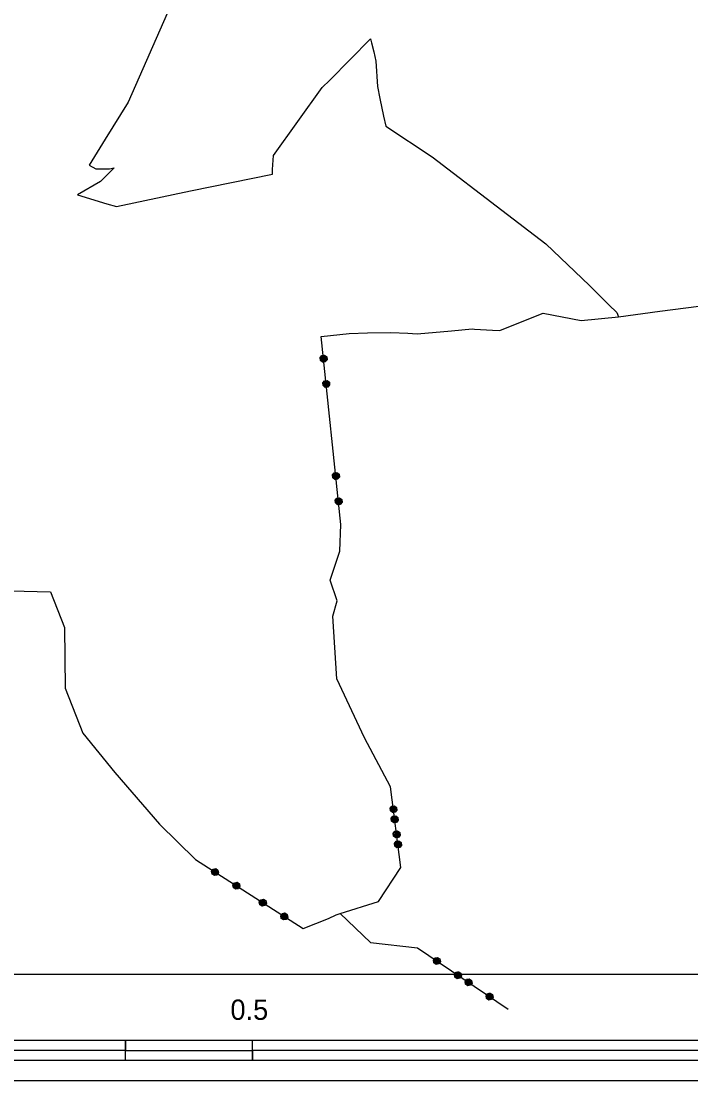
# Model space of a CAD drawing. Extents: x -783999 to -781353, y -1138035 to -1135203.
# Drawn here: x -783274 to -782747, y -1138035 to -1137201 of the extents above; entities that cross this region are included whole.
import ezdxf

# ---------------------------------------------------------------- set-up
doc = ezdxf.new("R2010")
doc.units = 0
for name, color, linetype in [('GR_MER', 7, 'Continuous'), ('HRA_KU', 7, 'Continuous'), ('OVNE_PRE', 7, 'Continuous'), ('OVNE_SET', 7, 'Continuous')]:
    doc.layers.add(name, color=color, linetype=linetype)

msp = doc.modelspace()

# ---------------------------------------------------------------- linework, layer by layer
at = {"layer": 'GR_MER'}
for points in [[(-781937.12, -1137951.24), (-781937.12, -1138035.25), (-783615.31, -1138035.25), (-783615.31, -1137951.24), (-781937.12, -1137951.24)], [(-783192.03, -1138011.25), (-783192.03, -1138003.25), (-783092.03, -1138003.25)], [(-783192.03, -1138019.25), (-783292.03, -1138019.25), (-783292.03, -1138011.25)], [(-782592.03, -1138019.25), (-783092.03, -1138019.25), (-783092.03, -1138011.25)]]:
    msp.add_lwpolyline(points, dxfattribs=at)
for points in [[(-783192.03, -1138011.25), (-783292.03, -1138011.25), (-783292.03, -1138003.25), (-783192.03, -1138003.25)], [(-782592.03, -1138011.25), (-783092.03, -1138011.25), (-783092.03, -1138003.25), (-782592.03, -1138003.25)], [(-783092.03, -1138019.25), (-783192.03, -1138019.25), (-783192.03, -1138011.25), (-783092.03, -1138011.25)]]:
    msp.add_lwpolyline(points, close=True, dxfattribs=at)
at = {"layer": 'HRA_KU'}
for points in [[(-783022.89, -1137903.48), (-782992.86, -1137893.9), (-782975.31, -1137867.31), (-782983.29, -1137803.78), (-783003.83, -1137765.01), (-783025.51, -1137718.72), (-783028.67, -1137669.18), (-783025.47, -1137657.3), (-783030.85, -1137641.03), (-783023.21, -1137618.17), (-783022.37, -1137597.08), (-783037.93, -1137448.95), (-783015.95, -1137446.62), (-783001.44, -1137446.28), (-782983.19, -1137445.77), (-782969.65, -1137446.47), (-782962.27, -1137446.92), (-782935.25, -1137444.56), (-782919.09, -1137443.08), (-782917.36, -1137443.17), (-782902.99, -1137444.14), (-782897.35, -1137444.43), (-782865.42, -1137431.53), (-782863.19, -1137430.59), (-782833.35, -1137436.41), (-782803.82, -1137433.57)], [(-783038.74, -1137465.69), (-783037.39, -1137464.02), (-783035.24, -1137463.79), (-783033.57, -1137465.14), (-783033.34, -1137467.29), (-783034.7, -1137468.96), (-783036.85, -1137469.19), (-783038.52, -1137467.83), (-783038.74, -1137465.69), (-783038.4, -1137465.89), (-783038.2, -1137467.8), (-783037.49, -1137468.37), (-783037.83, -1137465.19), (-783037.26, -1137464.48), (-783036.79, -1137468.94), (-783036.16, -1137468.87), (-783036.62, -1137464.42), (-783035.98, -1137464.35), (-783035.52, -1137468.81), (-783034.88, -1137468.74), (-783035.35, -1137464.28), (-783034.65, -1137464.85), (-783034.31, -1137468.04), (-783033.74, -1137467.33), (-783033.94, -1137465.42)], [(-783036.66, -1137485.58), (-783035.31, -1137483.91), (-783033.16, -1137483.68), (-783031.49, -1137485.04), (-783031.26, -1137487.18), (-783032.62, -1137488.85), (-783034.77, -1137489.08), (-783036.44, -1137487.72), (-783036.66, -1137485.58), (-783036.33, -1137485.62), (-783036.13, -1137487.53), (-783035.43, -1137488.1), (-783035.76, -1137484.92), (-783035.19, -1137484.22), (-783034.73, -1137488.67), (-783034.09, -1137488.61), (-783034.56, -1137484.15), (-783033.92, -1137484.08), (-783033.46, -1137488.54), (-783032.82, -1137488.47), (-783033.28, -1137484.02), (-783032.58, -1137484.59), (-783032.25, -1137487.77), (-783031.68, -1137487.07), (-783031.88, -1137485.16)], [(-783029.03, -1137558.12), (-783027.68, -1137556.45), (-783025.53, -1137556.23), (-783023.86, -1137557.58), (-783023.63, -1137559.73), (-783024.99, -1137561.4), (-783027.14, -1137561.62), (-783028.81, -1137560.27), (-783029.03, -1137558.12), (-783028.69, -1137558.33), (-783028.49, -1137560.24), (-783027.79, -1137560.81), (-783028.12, -1137557.62), (-783027.55, -1137556.92), (-783027.08, -1137561.38), (-783026.45, -1137561.31), (-783026.91, -1137556.85), (-783026.27, -1137556.79), (-783025.81, -1137561.24), (-783025.17, -1137561.18), (-783025.64, -1137556.72), (-783024.94, -1137557.29), (-783024.6, -1137560.47), (-783024.03, -1137559.77), (-783024.23, -1137557.86)], [(-783026.95, -1137578.01), (-783025.6, -1137576.34), (-783023.45, -1137576.12), (-783021.78, -1137577.47), (-783021.55, -1137579.62), (-783022.91, -1137581.29), (-783025.06, -1137581.51), (-783026.73, -1137580.16), (-783026.95, -1137578.01), (-783026.62, -1137578.06), (-783026.42, -1137579.97), (-783025.72, -1137580.54), (-783026.05, -1137577.36), (-783025.48, -1137576.65), (-783025.02, -1137581.11), (-783024.38, -1137581.04), (-783024.85, -1137576.59), (-783024.21, -1137576.52), (-783023.75, -1137580.98), (-783023.11, -1137580.91), (-783023.57, -1137576.45), (-783022.87, -1137577.02), (-783022.54, -1137580.21), (-783021.97, -1137579.5), (-783022.17, -1137577.59)], [(-783303.13, -1137648.78), (-783250.99, -1137650.16), (-783239.9, -1137678.31), (-783239.48, -1137726.05), (-783225.61, -1137761.46), (-783200.39, -1137792.47), (-783165.09, -1137833.16), (-783136.89, -1137860.91), (-783052.16, -1137915.26), (-783032.08, -1137907.33), (-783026.02, -1137904.41), (-783022.89, -1137903.48)], [(-782983.77, -1137820.53), (-782982.45, -1137818.83), (-782980.31, -1137818.56), (-782978.61, -1137819.88), (-782978.34, -1137822.02), (-782979.66, -1137823.72), (-782981.8, -1137823.99), (-782983.5, -1137822.67), (-782983.77, -1137820.53), (-782983.42, -1137820.73), (-782983.18, -1137822.63), (-782982.47, -1137823.19), (-782982.87, -1137820.01), (-782982.31, -1137819.3), (-782981.75, -1137823.74), (-782981.12, -1137823.66), (-782981.68, -1137819.22), (-782981.04, -1137819.14), (-782980.48, -1137823.58), (-782979.85, -1137823.5), (-782980.41, -1137819.06), (-782979.69, -1137819.61), (-782979.29, -1137822.79), (-782978.74, -1137822.07), (-782978.98, -1137820.17)], [(-782982.77, -1137828.5), (-782981.45, -1137826.8), (-782979.31, -1137826.53), (-782977.61, -1137827.85), (-782977.34, -1137829.99), (-782978.66, -1137831.69), (-782980.8, -1137831.96), (-782982.5, -1137830.64), (-782982.77, -1137828.5), (-782982.42, -1137828.7), (-782982.18, -1137830.6), (-782981.47, -1137831.16), (-782981.87, -1137827.98), (-782981.31, -1137827.27), (-782980.75, -1137831.71), (-782980.12, -1137831.63), (-782980.68, -1137827.19), (-782980.04, -1137827.11), (-782979.48, -1137831.55), (-782978.85, -1137831.47), (-782979.41, -1137827.03), (-782978.69, -1137827.58), (-782978.29, -1137830.76), (-782977.74, -1137830.04), (-782977.98, -1137828.14)], [(-782981.27, -1137840.37), (-782979.95, -1137838.68), (-782977.81, -1137838.41), (-782976.11, -1137839.73), (-782975.84, -1137841.87), (-782977.16, -1137843.57), (-782979.3, -1137843.84), (-782981, -1137842.52), (-782981.27, -1137840.37), (-782980.94, -1137840.41), (-782980.7, -1137842.32), (-782979.99, -1137842.87), (-782980.39, -1137839.7), (-782979.83, -1137838.98), (-782979.27, -1137843.43), (-782978.64, -1137843.35), (-782979.2, -1137838.9), (-782978.56, -1137838.82), (-782978, -1137843.27), (-782977.37, -1137843.19), (-782977.93, -1137838.74), (-782977.21, -1137839.3), (-782976.81, -1137842.47), (-782976.26, -1137841.76), (-782976.5, -1137839.85)], [(-782980.27, -1137848.34), (-782978.95, -1137846.64), (-782976.81, -1137846.37), (-782975.11, -1137847.69), (-782974.84, -1137849.83), (-782976.16, -1137851.53), (-782978.3, -1137851.8), (-782980, -1137850.48), (-782980.27, -1137848.34), (-782979.94, -1137848.38), (-782979.7, -1137850.29), (-782978.99, -1137850.84), (-782979.39, -1137847.67), (-782978.83, -1137846.95), (-782978.27, -1137851.4), (-782977.64, -1137851.32), (-782978.2, -1137846.87), (-782977.56, -1137846.79), (-782977, -1137851.24), (-782976.37, -1137851.16), (-782976.93, -1137846.71), (-782976.21, -1137847.27), (-782975.81, -1137850.44), (-782975.26, -1137849.73), (-782975.5, -1137847.82)], [(-783119.15, -1137869.25), (-783118.69, -1137871.35), (-783119.85, -1137873.17), (-783121.95, -1137873.63), (-783123.77, -1137872.46), (-783124.23, -1137870.36), (-783123.06, -1137868.55), (-783120.96, -1137868.09), (-783119.15, -1137869.25), (-783119.39, -1137869.48), (-783121, -1137868.44), (-783121.89, -1137868.64), (-783119.19, -1137870.36), (-783119, -1137871.25), (-783122.77, -1137868.83), (-783123.12, -1137869.37), (-783119.34, -1137871.79), (-783119.69, -1137872.32), (-783123.46, -1137869.91), (-783123.81, -1137870.44), (-783120.04, -1137872.86), (-783120.92, -1137873.06), (-783123.61, -1137871.33), (-783123.42, -1137872.21), (-783121.8, -1137873.25)], [(-783102.31, -1137880.05), (-783101.85, -1137882.15), (-783103.02, -1137883.97), (-783105.12, -1137884.43), (-783106.94, -1137883.26), (-783107.39, -1137881.16), (-783106.23, -1137879.34), (-783104.13, -1137878.88), (-783102.31, -1137880.05), (-783102.68, -1137880.19), (-783104.3, -1137879.15), (-783105.19, -1137879.34), (-783102.49, -1137881.07), (-783102.3, -1137881.96), (-783106.07, -1137879.54), (-783106.41, -1137880.08), (-783102.64, -1137882.49), (-783102.99, -1137883.03), (-783106.76, -1137880.62), (-783107.11, -1137881.15), (-783103.33, -1137883.57), (-783104.22, -1137883.77), (-783106.91, -1137882.04), (-783106.72, -1137882.92), (-783105.1, -1137883.96)], [(-783081.55, -1137893.37), (-783081.09, -1137895.47), (-783082.26, -1137897.28), (-783084.36, -1137897.74), (-783086.18, -1137896.58), (-783086.64, -1137894.48), (-783085.47, -1137892.66), (-783083.37, -1137892.2), (-783081.55, -1137893.37), (-783081.79, -1137893.59), (-783083.41, -1137892.56), (-783084.29, -1137892.75), (-783081.6, -1137894.48), (-783081.41, -1137895.36), (-783085.18, -1137892.94), (-783085.52, -1137893.48), (-783081.75, -1137895.9), (-783082.1, -1137896.44), (-783085.87, -1137894.02), (-783086.21, -1137894.56), (-783082.44, -1137896.98), (-783083.33, -1137897.17), (-783086.02, -1137895.44), (-783085.83, -1137896.33), (-783084.21, -1137897.36)], [(-783064.72, -1137904.16), (-783064.26, -1137906.26), (-783065.42, -1137908.08), (-783067.52, -1137908.54), (-783069.34, -1137907.37), (-783069.8, -1137905.27), (-783068.63, -1137903.46), (-783066.53, -1137903), (-783064.72, -1137904.16), (-783065.09, -1137904.3), (-783066.71, -1137903.27), (-783067.59, -1137903.46), (-783064.9, -1137905.19), (-783064.7, -1137906.07), (-783068.48, -1137903.65), (-783068.82, -1137904.19), (-783065.05, -1137906.61), (-783065.4, -1137907.15), (-783069.17, -1137904.73), (-783069.51, -1137905.27), (-783065.74, -1137907.69), (-783066.62, -1137907.88), (-783069.32, -1137906.15), (-783069.13, -1137907.04), (-783067.51, -1137908.07)], [(-783022.89, -1137903.48), (-782999.02, -1137926.43), (-782962.01, -1137930.52), (-782890.78, -1137978.73)], [(-782944.47, -1137939.3), (-782944.07, -1137941.41), (-782945.28, -1137943.19), (-782947.39, -1137943.6), (-782949.18, -1137942.39), (-782949.59, -1137940.28), (-782948.37, -1137938.49), (-782946.26, -1137938.08), (-782944.47, -1137939.3), (-782944.72, -1137939.52), (-782946.31, -1137938.44), (-782947.2, -1137938.61), (-782944.55, -1137940.4), (-782944.38, -1137941.29), (-782948.09, -1137938.78), (-782948.45, -1137939.31), (-782944.74, -1137941.82), (-782945.1, -1137942.35), (-782948.81, -1137939.84), (-782949.16, -1137940.37), (-782945.45, -1137942.88), (-782946.34, -1137943.05), (-782948.99, -1137941.26), (-782948.82, -1137942.15), (-782947.23, -1137943.22)], [(-782927.91, -1137950.51), (-782927.51, -1137952.62), (-782928.72, -1137954.41), (-782930.83, -1137954.81), (-782932.62, -1137953.6), (-782933.02, -1137951.49), (-782931.81, -1137949.7), (-782929.7, -1137949.3), (-782927.91, -1137950.51), (-782928.29, -1137950.64), (-782929.88, -1137949.56), (-782930.77, -1137949.73), (-782928.12, -1137951.53), (-782927.95, -1137952.42), (-782931.66, -1137949.9), (-782932.02, -1137950.43), (-782928.31, -1137952.95), (-782928.67, -1137953.48), (-782932.38, -1137950.96), (-782932.74, -1137951.49), (-782929.03, -1137954.01), (-782929.91, -1137954.18), (-782932.56, -1137952.38), (-782932.39, -1137953.27), (-782930.8, -1137954.35)], [(-782919.62, -1137956.12), (-782919.21, -1137958.23), (-782920.43, -1137960.02), (-782922.54, -1137960.42), (-782924.32, -1137959.21), (-782924.73, -1137957.1), (-782923.52, -1137955.31), (-782921.41, -1137954.91), (-782919.62, -1137956.12), (-782919.87, -1137956.34), (-782921.46, -1137955.26), (-782922.35, -1137955.43), (-782919.7, -1137957.23), (-782919.52, -1137958.11), (-782923.23, -1137955.6), (-782923.59, -1137956.13), (-782919.88, -1137958.64), (-782920.24, -1137959.17), (-782923.95, -1137956.66), (-782924.31, -1137957.19), (-782920.6, -1137959.7), (-782921.49, -1137959.88), (-782924.14, -1137958.08), (-782923.97, -1137958.97), (-782922.38, -1137960.05)], [(-782903.06, -1137967.33), (-782902.65, -1137969.44), (-782903.86, -1137971.23), (-782905.98, -1137971.64), (-782907.76, -1137970.42), (-782908.17, -1137968.31), (-782906.96, -1137966.53), (-782904.85, -1137966.12), (-782903.06, -1137967.33), (-782903.44, -1137967.46), (-782905.03, -1137966.38), (-782905.92, -1137966.56), (-782903.27, -1137968.35), (-782903.1, -1137969.24), (-782906.81, -1137966.73), (-782907.16, -1137967.26), (-782903.45, -1137969.77), (-782903.81, -1137970.3), (-782907.52, -1137967.79), (-782907.88, -1137968.32), (-782904.17, -1137970.83), (-782905.06, -1137971), (-782907.71, -1137969.2), (-782907.54, -1137970.09), (-782905.95, -1137971.17)]]:
    msp.add_lwpolyline(points, dxfattribs=at)
at = {"layer": 'OVNE_PRE'}
msp.add_lwpolyline([(-782803.82, -1137433.57), (-782771.49, -1137429.11), (-782740.81, -1137425.16)], dxfattribs=at)
at = {"layer": 'OVNE_SET'}
for p, q in [((-783229.81, -1137337.35), (-783206.56, -1137344.51)), ((-783206.56, -1137344.51), (-783199.07, -1137346.7)), ((-782805.18, -1137430.27), (-782803.82, -1137433.57))]:
    msp.add_line(p, q, dxfattribs=at)
for points in [[(-783181.36, -1137015.06), (-783106.69, -1137048.4), (-783104.2, -1137056.26), (-783127.29, -1137106.83), (-783130.68, -1137114.91), (-783155.41, -1137173.98), (-783156.32, -1137188.2), (-783189.81, -1137264.6), (-783207.86, -1137293.68), (-783220.59, -1137314.2), (-783215.29, -1137317.12), (-783204.45, -1137317.06)], [(-783199.07, -1137346.7), (-783140.76, -1137334.2), (-783076.37, -1137321.24), (-783076.16, -1137317.5), (-783075.56, -1137306.53), (-783037.08, -1137253.02), (-783031.17, -1137247.06), (-782999.06, -1137214.72)], [(-782999.06, -1137214.72), (-782998.27, -1137217.71), (-782996.39, -1137224.79), (-782994.88, -1137232.21), (-782993.74, -1137252.17), (-782991.76, -1137261.49), (-782988.76, -1137275.57), (-782987.08, -1137283.31), (-782950.57, -1137307.53), (-782895.81, -1137349.57), (-782861.15, -1137376.17), (-782826.81, -1137408.94), (-782811.51, -1137424.03), (-782805.18, -1137430.27)], [(-783204.45, -1137317.06), (-783200.86, -1137316.14), (-783211.62, -1137326.95), (-783229.81, -1137337.35)]]:
    msp.add_lwpolyline(points, dxfattribs=at)

# ---------------------------------------------------------------- texts
at = {"layer": 'GR_MER'}
msp.add_text('0.5', height=16, dxfattribs=at).set_placement((-783109.35, -1137987.25))

doc.saveas('drawing.dxf')
